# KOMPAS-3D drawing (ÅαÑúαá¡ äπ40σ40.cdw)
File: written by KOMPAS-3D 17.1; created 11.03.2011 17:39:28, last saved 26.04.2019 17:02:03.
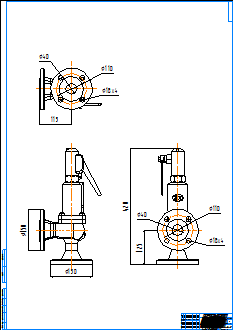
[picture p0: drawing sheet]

Sheet 1: A0, portrait

Title block, sheet 1: name: Прегран Ду40х40; material: Внимание! Данный продукт является объектом авторского права ООО «Торговый Дом АДЛ». / Запрещается изменение, копирование, распространение / (в том числе путем копирования на другие сайты и ресурсы в Интернете) / или любое иное использование информации и объектов без предварительного / согласия правообладателя (ООО «Торговый Дом АДЛ»).; scale: 1:1; sheets: 1; organisation: ООО "Торговый дом АДЛ"; sheet format: A0; stored path: C:\Users\tra\Desktop\2д чертежи\Предохранительные клапаны ПРЕГРАН\ПРЕГРАН 096\ПРЕГРАН КПП 096-03-40\KOMPAS 2D\Прегран Ду40х40.cdw

Views: Спереди 1, Проекционный вид 2, Проекционный вид 3
Dimensions and other numbers on the sheet: 150; 125; 115; 110; 18; 40; 420; 1:1; 1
